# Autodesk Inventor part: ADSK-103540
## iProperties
Shininess: 20.0
Created: 2001-04
Part Number: ADSK-103540
Document SubType Name: Modeling
Designer: Administrator
Stock Number: ADSK-103540
Density: 1 g/cm^3
Density: 0.0
Volumn: 0.0
Area: 0.0
PropertySet Name: Model Information
Control State: 0
Master: False
Checked Out: False
Author: Administrator
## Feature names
1. Extrusion1
2. Extrusion2
3. Extrusion3
4. Chamfer1
5. Chamfer2
6. Hole1
7. Hole2
8. Hole3
9. Hole4
10. Hole5
11. Extrusion4
12. Fillet1
13. Extrusion5
14. Extrusion6
15. Rectangular Pattern1
16. Rectangular Pattern2
17. Rectangular Pattern3
